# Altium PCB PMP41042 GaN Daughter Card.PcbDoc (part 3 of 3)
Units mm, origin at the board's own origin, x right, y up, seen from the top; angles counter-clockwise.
Board outline 43.43 x 37.33 mm, 6 copper layers (Top Layer, MidLayer1, MidLayer2, MidLayer3, MidLayer4, Bottom Layer), stack 1.844 mm thick; 57 components, 55 nets, 240 pads, 238 vias.
Unrouted connection lines stored in the file: 15.
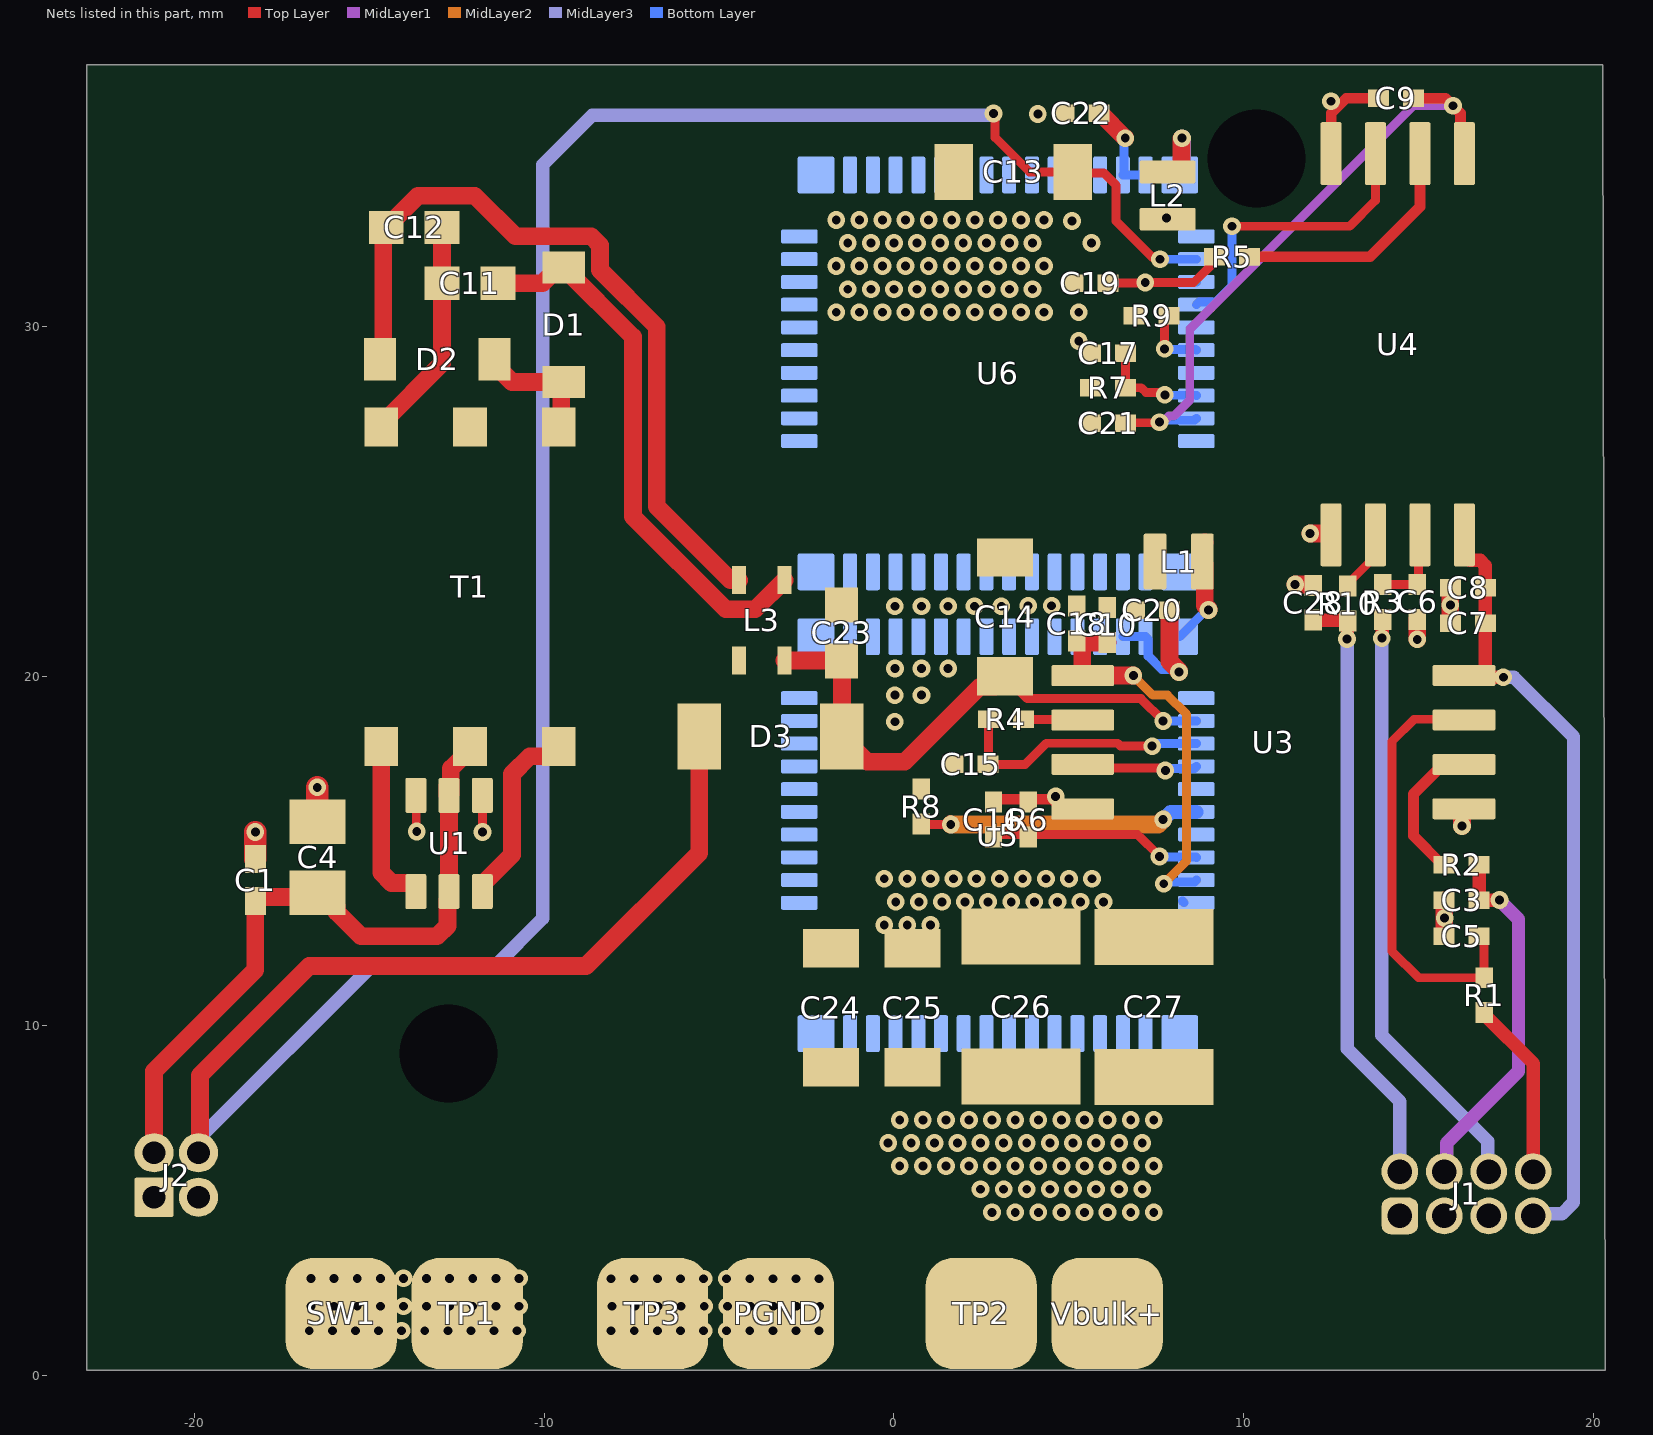
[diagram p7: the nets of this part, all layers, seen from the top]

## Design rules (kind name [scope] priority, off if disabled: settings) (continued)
SilkToSolderMaskClearance SilkToComponentPadClearance [(IsPad or IsFill or IsRegion) and InAnycomponent] p1: minsilkscreentomaskgap=0.025 clearancetoexposedcopper=TRUE
SilkToSolderMaskClearance "Silk to Solder Mask Opening" [All] p2: minsilkscreentomaskgap=0.025 clearancetoexposedcopper=FALSE
SolderMaskExpansion [All] p1: expansion=0.05 istentingtop=FALSE
Width [All] p1: maxlimit=2.54 minlimit=0.152 preferedwidth=0.254 substack1={A02F224D-4808-492E-A71F-5F5656FBF0D4} substack2={B838D286-A00B-4EE2-88E1-F79279CC64B4} substack3={0D253197-D122-4D2B-9584-B8C12AA3806F} substack4={88BCB183-C685-456E-B90A-365A53404C2C} substack5={4C8C2325-90D5-40B8-8B6B-4F66D44EFE25} substack6={553D66F5-99EF-40B1-BA7C-73E3B04B176F} substack7={FF0C9878-5A48-402E-B013-8E2EEFCEDCCB} substack8={5BB5B65B-6C7F-4868-A6AE-66DD57ADDCBD} substack9={65866CD6-1929-42AF-BAA8-019D5E6BA212} substack10={590F0BEA-1E04-4904-B9C9-D9D160075BC2} substack11={B2AC4F48-1A5F-44D7-A91B-3BAADFDAAED0} substack12={DD3D4156-A54D-4E1F-B7FF-E5EF72C45496} substack13={7CC4AE65-1EB7-43C1-8FCA-3677EE54F737} substack14={E8C37195-128A-4AA0-B681-9B6788FCEC2F} substack15={92E0C252-34CC-4501-B85F-B111C59C3287} substack16={732F7058-E977-446F-8A06-ECA871B5D75E} substack17={990DA1BC-A1DE-47D8-A675-B5A4E74B5332} checkconnectedcopper=TRUE
14 further rules are at their usual default settings.

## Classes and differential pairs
component class Header: J1
net class INGND: 5Vp 5Vs 12V AGND Bot_FET_FAULT1 LEG1_HS LEG1_LS NetC5_1 NetC6_1 NetR2_2 NetR10_2 NetU2_12 NetU3_12 PGND Top_FET_FAULT1
net class PGND: 5V_L1 5Vp 12V FAULT_LS NetC17_2 NetC19_2 NetC22_1 NetL2_2 NetR5_1 NetR9_2 NetT1_4 NetT1_6 NetU2_5 NetU6_43 NetU6_47 NetU6_48 NetU6_52 PGND PGND_NC1 PGND_NC2 PGND_NC3 PGND_NC4 PGND_NC5 TEMP_LS
net class VHV: Vbulk+ VHV_NC1 VHV_NC2
net class VSW1NET: 5V_H1 12V ISO_12V_H1 NCT1 NetC11_1 NetC11_2 NetC12_2 NetC15_2 NetC16_2 NetC20_1 NetD1_2 NetL1_2 NetR4_2 NetR8_2 NetT1_5 NetU3_3 NetU3_5 NetU5_43 NetU5_47 NetU5_48 NetU5_52 SW1 SW1_NC1 SW1_NC2 SW1_NC3 SW1_NC4 SW1_NC5 SW1_NC6 SW1_NC7 TEMP_HS_NC1
component class LMG352X: U5 U6

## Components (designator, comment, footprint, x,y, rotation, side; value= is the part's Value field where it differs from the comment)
C1 "C1005X7R1H104K050BB" 0402 -18.258,14.169 r90 top value=0.1uF
C3 "C1005C0G1H680J050BA" 0402L 16.235,13.591 r180 top value=68pF
C4 "GCM21BR71C475KA73L" 0805_HV -16.48,14.819 r90 top value=4.7uF
C5 "04025A101FAT2A" 0402L 16.233,12.56 r180 top value=100pF
C6 "04025A101FAT2A" 0402L 14.965,22.123 r270 top value=100pF
C7 "C1005X7R1H104K050BB" 0402L 16.413,21.514 r180 top value=0.1uF
C8 "C1005X7R1H104K050BB" 0402L 16.413,22.53 r0 top value=0.1uF
C9 "C1005X7R1H104K050BB" 0402L 14.355,36.525 r0 top value=0.1uF
C10 "C1005X7R1H104K050BB" 0402L 6.096,21.463 r90 top value=0.1uF
C11 "C1608X5R1V475K080AC" 0603 -12.121,31.233 r180 top value=4.7uF
C12 "C1608X5R1V475K080AC" 0603 -13.715,32.829 r180 top value=4.7uF
C13 "C3216X7R1E106M160AE" 1206_190 3.417,34.416 r180 top value=10uF
C14 "C3216X7R1E106M160AE" 1206_190 3.179,21.692 r90 top value=10uF
C15 "04025A101FAT2A" 0402L 2.195,17.475 r0 top value=100pF
C16 "04025A101FAT2A" 0402L 2.848,15.9 r270 top value=100pF
C17 "04025A101FAT2A" 0402L 6.126,29.235 r0 top value=100pF
C18 "CL05B224KO5NNNC" 0402L 5.228,21.504 r270 top value=0.22uF
C19 "04025A101FAT2A" 0402L 5.616,31.233 r0 top value=100pF
C20 "GRT155R61E225KE13D" 0402L 7.383,21.89 r180 top value=2.2uF
C21 "CL05B224KO5NNNC" 0402L 6.126,27.229 r0 top value=0.22uF
C22 "GRT155R61E225KE13D" 0402L 5.364,36.093 r180 top value=2.2uF
C23 "C1608X5R1V475K080AC" 0603 -1.494,21.234 r90 top value=4.7uF
C24 "C1206C223KDRACTU" 1206_190 -1.799,10.516 r90 top value=0.022uF
C25 "C1206C223KDRACTU" 1206_190 0.538,10.516 r90 top value=0.022uF
C26 "C1812W104KDRACTU" 1812_254 3.637,10.553 r90 top value=0.1uF
C27 "C1812W104KDRACTU" 1812_254 7.433,10.541 r90 top value=0.1uF
C28 "C1005C0G1H680J050BA" 0402L 11.993,22.098 r90 top value=68pF
D1 "MBR0520LT1G" SOD-123 -9.444,30.048 r270 top value=20V
D2 "MBR0520LT1G" SOD-123 -13.051,29.058 r180 top value=20V
D3 "ES1JAF" SMAF -3.526,18.279 r180 top value=600V
J1 "GRPB042MWCN-RC" Sullins_GRPB042MWCN 16.373,5.2 r90 top
J2 "M50-3900242" FP-M50-3900242_HDR4-MFG -20.519,2.1 r180 top
L1 "SDEM20161T-4R7MS" FP-SDEM20161T-4R7MS_SMD2-MFG 8.144,23.277 r0 top
L2 "SDEM20161T-4R7MS" FP-SDEM20161T-4R7MS_SMD2-MFG 7.829,33.741 r90 top
L3 "ACM2520-601-2P-T002" TDK_ACM2520-2P -3.78,21.593 r270 top
PGND "3621-0-32-15-00-00-08-0" Mill-Max_3621-0-32-xx-00-00-08-0 -3.302,-0.61 r0 top
R1 "RC0402FR-0749R9L" 0402L 16.878,10.876 r90 top value=49.9
R2 "CRCW0402300RJNED" 0402L 16.233,14.605 r180 top value=300
R3 "RC0402FR-0749R9L" 0402L 13.974,22.123 r90 top value=49.9
R4 "RC0402FR-0749R9L" 0402L 3.205,18.771 r0 top value=49.9
R5 "RC0402FR-0749R9L" 0402L 9.669,31.988 r180 top value=49.9
R6 "ERJ-2RKF2003X" 0402L 3.84,15.9 r270 top value=200k
R7 "ERJ-2RKF2003X" 0402L 6.128,28.247 r0 top value=200k
R8 "ERJ-2GE0R00X" 0402L 0.781,16.267 r270 top value=0
R9 "ERJ-2GE0R00X" 0402L 7.37,30.302 r0 top value=0
R10 "CRCW0402300RJNED" 0402L 12.984,22.071 r90 top value=300
SW1 "3621-0-32-15-00-00-08-0" Mill-Max_3621-0-32-xx-00-00-08-0 -15.8,-0.61 r0 top
T1 "760390014" Wurth_760390013 -12.121,22.555 r270 top value=475uH
TP1 "3621-0-32-15-00-00-08-0" Mill-Max_3621-0-32-xx-00-00-08-0 -12.2,-0.61 r0 top
TP2 "3621-0-32-15-00-00-08-0" Mill-Max_3621-0-32-xx-00-00-08-0 2.498,-0.61 r0 top
TP3 "3621-0-32-15-00-00-08-0" Mill-Max_3621-0-32-xx-00-00-08-0 -6.902,-0.61 r0 top
U1 "SN6505BDBVR" DBV0006A_N -12.719,15.215 r90 top
U3 "ISO7721FDWV" DWV0008A#1 10.85,18.11 r0 top
U4 "ISO7721FDWV" DWV0008A#2 14.406,29.489 r270 top
U5 "XMG3522R030QRQSTQ1" RQS0052A-MFG 2.972,15.454 r90 bottom
U6 "XMG3522R030QRQSTQ1" RQS0052A-MFG 2.972,28.655 r90 bottom
Vbulk+ "3621-0-32-15-00-00-08-0" Mill-Max_3621-0-32-xx-00-00-08-0 6.098,-0.61 r0 top

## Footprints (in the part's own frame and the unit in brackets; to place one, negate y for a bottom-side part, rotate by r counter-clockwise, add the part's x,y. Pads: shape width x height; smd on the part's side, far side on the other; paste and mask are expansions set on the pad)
0402 [mm] "0402 from SM-752 data"
  rect 0.8x0.6 smd: 1(-0.6,0) 2(0.6,0)
  silkscreen extent -1.22,-0.52 1.22,0.52, body extent -0.55,-0.3 0.55,0.3, height 0.6
0402L [mm] "0402 from SM-752 data"
  rect 0.6x0.5 smd: 1(-0.5,0) 2(0.5,0)
  body extent -0.55,-0.3 0.55,0.3, height 0.6
0603 [mm] "0603 from SM-752 data"
  rect 1x0.95 smd: 1(-0.8,0) 2(0.8,0)
  silkscreen extent -1.52,-0.69 1.52,0.69, body extent -0.87,-0.47 0.87,0.47, height 1
0805_HV [mil] "0805 with 30mil clearance between pads"
  rect 50x63 smd: 1(-40,0) 2(40,0)
  silkscreen extent -74,-40 74,40, body extent -43,-29 43,29, height 57
1206_190 [mm] "1206_190"
  rect 1.1x1.6 smd: 1(-1.7,0) 2(1.7,0)
  silkscreen extent -0.9,-1 0.9,1, body extent -1.75,-0.95 1.75,0.95, height 1.9
1812_254 [mm] "SMD, 2-Leads, Body 4.8x3.4mm"
  rect 1.6x3.4 smd: 1(-2,0) 2(2,0)
  silkscreen extent -0.8,-1.7 0.8,1.7, body extent -2.4,-1.7 2.4,1.7, height 2.54
DBV0006A_N [mm] "SOT23, 6-Leads, Body 2.9x1.6mm, Pitch 0.95mm, Lead Span 2.8mm, IPC Medium Density"
  rrect17% 1x0.6 smd: 1(-1.375,0.95) 2(-1.375,0) 3(-1.375,-0.95) 4(1.375,-0.95) 5(1.375,0) 6(1.375,0.95)
  silkscreen extent -1.68,-1.55 0.5,1.55, body extent -1.42,-1.46 1.42,1.46, height 1.12
DWV0008A#1 [mm] "SOIC, 8-Leads, Body 5.95x7.6mm (max), Pitch 1.27mm"
  rrect17% 1.8x0.6 smd: 1(-5.45,1.905) 2(-5.45,0.635) 3(-5.45,-0.635) 4(-5.45,-1.905) 5(5.45,-1.905) 6(5.45,-0.635) 7(5.45,0.635) 8(5.45,1.905)
  silkscreen extent -6.25,-2.95 2.98,2.95, body extent -5.77,-2.92 5.77,2.93, height 2.67
DWV0008A#2 [mm] "SOIC, 8-Leads, Body 5.95x7.6mm (max), Pitch 1.27mm"
  rrect17% 1.8x0.6 smd: 1(-5.45,1.905) 2(-5.45,0.635) 3(-5.45,-0.635) 4(-5.45,-1.905) 5(5.45,-1.905) 6(5.45,-0.635) 7(5.45,0.635) 8(5.45,1.905)
  silkscreen extent -6.25,-2.95 2.98,2.95, body extent -5.77,-2.92 5.77,2.93, height 2.67
FP-M50-3900242_HDR4-MFG [mm]
  rrect9% 1.12x1.12 hole 0.65 paste-1000 mask+0: 1(0.635,-3)
  round 1.12 hole 0.65 paste-1000 mask+0: 2(0.635,-4.27) 3(-0.635,-3) 4(-0.635,-4.27)
  silkscreen extent -1.47,-3.12 1.87,0.58, body extent -1.57,-4.93 1.57,4.72, height 0.25
FP-SDEM20161T-4R7MS_SMD2-MFG [mm]
  rrect15% 0.65x1.6 smd paste+0 mask+0: 1(-0.675,0) 2(0.675,0)
  silkscreen extent -1.05,-1.22 1.05,1.2, body extent -1.15,-0.95 1.15,0.95, height 0.25
Mill-Max_3621-0-32-xx-00-00-08-0 [mm] "PCB Pin, 0.04\" DIA, R/A, Edge-Mount"
  rrect50% 3.18x3.18 smd: 1(0,2.388)
  body extent -1.59,-5.06 1.59,3.98, height 1.57
RQS0052A-MFG [mm]
  rrect10% 1.05x1.05 smd paste+0 mask+0: 1(-5.675,5.2) 16(-5.675,-5.2) 27(5.675,-5.2) 42(5.675,5.2)
  rrect25% 1.05x0.4 smd paste+0 mask+0: 2(-5.675,4.225) 3(-5.675,3.575) 4(-5.675,2.925) 5(-5.675,2.275) 6(-5.675,1.625) 7(-5.675,0.975) 8(-5.675,0.325) 9(-5.675,-0.325) 10(-5.675,-0.975) 11(-5.675,-1.625) 12(-5.675,-2.275) 13(-5.675,-2.925) 14(-5.675,-3.575) 15(-5.675,-4.225) 28(5.675,-4.225) 29(5.675,-3.575) 30(5.675,-2.925) 31(5.675,-2.275) 32(5.675,-1.625) 33(5.675,-0.975) 34(5.675,-0.325) 35(5.675,0.325) 36(5.675,0.975) 37(5.675,1.625) 38(5.675,2.275) 39(5.675,2.925) 40(5.675,3.575) 41(5.675,4.225)
  rrect25% 0.4x1.05 smd paste+0 mask+0: 17(-1.935,-5.675) 18(-1.285,-5.675) 19(-0.635,-5.675) 20(0.015,-5.675) 21(0.665,-5.675) 22(1.315,-5.675) 23(1.965,-5.675) 24(2.615,-5.675) 25(3.265,-5.675) 26(3.915,-5.675) 43(3.915,5.675) 44(3.265,5.675) 45(2.615,5.675) 46(1.965,5.675) 47(1.315,5.675) 48(0.665,5.675) 49(0.015,5.675) 50(-0.635,5.675) 51(-1.285,5.675) 52(-1.935,5.675)
  silkscreen extent -6.9,-6.05 4.77,6.05, body extent -6,-6 6,6, height 1
SMAF [mm] "SMD, 2-Leads, Body 3.8x2.5mm"
  rect 1.24x1.89 smd: 1(-2.04,0) 2(2.04,0)
  silkscreen extent -3.4,-1.3 2.8,1.3, body extent -2.35,-1.25 2.35,1.25, height 1
SOD-123 [mm] "On Semi recommended land pattern"
  rect 0.915x1.22 smd: 1(-1.637,0) 2(1.637,0)
  silkscreen extent -2.74,-1.17 2.03,1.17, body extent -1.93,-0.9 1.93,0.9, height 1.35
Sullins_GRPB042MWCN [mm] "Header, 1.27mm, 4x2, R/A, TH"
  rrect50% 1.05x1.05 hole 0.7: 1(-0.635,1.905)
  round 1.05 hole 0.7: 2(0.635,1.905) 3(-0.635,0.635) 4(0.635,0.635) 5(-0.635,-0.635) 6(0.635,-0.635) 7(-0.635,-1.905) 8(0.635,-1.905)
  body extent -5.28,-2.54 0.84,2.54, height 3.4
TDK_ACM2520-2P [mm] "SMD, 4-Leads, Body 2.5x2mm"
  rect 0.8x0.4 smd: 1(-1.15,0.65) 2(-1.15,-0.65) 3(1.15,-0.65) 4(1.15,0.65)
  silkscreen extent -1.45,-1.2 1.45,1.4, body extent -1.35,-1.1 1.35,1.1, height 1.3
Wurth_760390013 [mil] "Wurth"
  rect 44x38 smd: 1(-180,100) 2(-180,0) 3(-180,-100) 4(180,-100) 5(180,0) 6(180,100)
  silkscreen extent -190,-133 85,145, body extent -198,-135 198,130, height 166

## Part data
C1 C7 C8 C9 C10: library part CMP-0006297-2, "CAP, CERM, 0.1 uF, 50 V, +/- 10%, X7R, 0402", Alternate Manufacturer="Wurth Elektronik", Alternate PartNumber=885012205037, Cap_Case=0402, Manufacturer=TDK, Supplier Part Number 1=445-5932-1-ND, TempCo=X7R, Tolerance_%=10%, Value1="0.039064 ohm", Value2=50V, ValueDisplayed=0.1uF
C3 C28: library part CMP-0006251-2, "CAP, CERM, 68 pF, 50 V, +/- 5%, C0G/NP0, 0402", Alternate Manufacturer=Murata, Alternate PartNumber=GRM1555C1H680JA01D, Cap_Case=0402, Manufacturer=TDK, Supplier Part Number 1=445-1245-1-ND, TempCo=C0G/NP0, Tolerance_%=5%, Value1=Unknown, Value2=50V, ValueDisplayed=68pF
C4: library part CMP-0008020-2, "CAP, CERM, 4.7 uF, 16 V, +/- 10%, X7R, AEC-Q200 Grade 1, 0805", Cap_Case=0805, Manufacturer=MuRata, Supplier Part Number 1=490-5332-1-ND, TempCo=X7R, Tolerance_%=10%, Value1=Unknown, Value2=16V, ValueDisplayed=4.7uF
C5 C6 C15 C16 C17 C19: library part CMP-0006196-2, "CAP, CERM, 100 pF, 50 V, +/- 1%, C0G/NP0, 0402", Cap_Case=0402, Manufacturer=AVX, Supplier Part Number 1=478-3658-1-ND, TempCo=C0G/NP0, Tolerance_%=1%, Value1=Unknown, Value2=50V, ValueDisplayed=100pF
C11 C12 C23: library part CMP-0007022-5, "CAP, CERM, 4.7 uF, 35 V, +/- 10%, X5R, 0603", Cap_Case=0603, Manufacturer=TDK, Supplier Part Number 1=445-9064-1-ND, TempCo=X5R, Tolerance_%=10%, Value1="0.003728 ohm", Value2=35V, ValueDisplayed=4.7uF
C13 C14: library part CMP-0008692-2, "CAP, CERM, 10 uF, 25 V, +/- 20%, X7R, 1206_190", Cap_Case=1206, Manufacturer=TDK, Supplier Part Number 1=445-6812-1-ND, TempCo=X7R, Tolerance_%=20%, Value1=Unknown, Value2=25V, ValueDisplayed=10uF
C18 C21: library part CMP-0860563-1, "CAP, CERM, 0.22 µF, 16 V,+/- 10%, X7R, 0402", Cap_Case=0402, Manufacturer="Samsung Electro-Mechanics", TempCo=X7R, Tolerance_%=10%, Value2=16V, ValueDisplayed=0.22µF
C20 C22: library part CMP-0006716-2, "CAP, CERM, 2.2 uF, 25 V, +/- 10%, X5R, AEC-Q200 Grade 3, 0402", Cap_Case=0402, Manufacturer=MuRata, Supplier Part Number 1=490-12267-1-ND, TempCo=X5R, Tolerance_%=10%, Value1=Unknown, Value2=25V, ValueDisplayed=2.2uF
C24 C25: library part CMP-0084048-1, "CAP, CERM, 0.022 µF, 1000 V,+/- 10%, X7R, AEC-Q200 Grade 1, 1206", Cap_Case=1206, Manufacturer=Kemet, TempCo=X7R, Tolerance_%=10%, Value2=1000V, ValueDisplayed=0.022µF
C26 C27: library part CMP-0009326-2, "CAP, CERM, 0.1 uF, 1000 V, +/- 10%, X7R, 1812", Cap_Case=1812, Manufacturer=Kemet, Supplier Part Number 1=399-6523-1-ND, TempCo=X7R, Tolerance_%=10%, Value1=Unknown, Value2=1000V, ValueDisplayed=0.1uF
D1 D2: library part CMP-0028524-2, "Diode, Schottky, 20 V, 0.5 A, SOD-123", Manufacturer="ON Semiconductor", Value1=0.5A, Value2=0.385V
D3: library part CMP-0029162-2, "Diode, Ultrafast, 600 V, 1 A, AEC-Q101, SMAF", Manufacturer="Fairchild Semiconductor", Value1=1A, Value2=1.7V
J1: library part CMP-0086278-1, "Header, 1.27mm, 4x2, Gold, R/A, TH", Current_A=1A, Manufacturer="Sullins Connector Solutions", Voltage_V=500V
J2: library part CMP-0097643-1, Current_A=1A, Digikey Part Number=M50-3900242-ND, Manufacturer=Harwin, Mouser Part Number=855-M50-3900242, Operating Temperature Range="-40°C to +105°C"
L1 L2: library part CMP-0089347-1, "4.7µH Unshielded Inductor 1.1A 426mOhm Max 0806 (2016 Metric)", Digikey Part Number=2037-SDEM20161T-4R7MSCT-ND, Manufacturer=Cyntec, Operating Temperature Range="-55°C to +125°C", Test Frequency=1MHz, Tolerance_%=20%
L3: library part CMP-0013161-2, "Coupled inductor, 0.2 A, 0.45 ohm, SMD", Manufacturer=TDK, Supplier Part Number 1=445-8930-1-ND
PGND SW1 TP1 TP2 TP3 Vbulk+: library part CMP-0082316-1, Manufacturer=Mill-Max, Supplier Part Number 1=575-3621032150000
R1 R3 R4 R5: library part CMP-0026738-1, "RES, 49.9, 1%, 0.063 W, 0402", Manufacturer="Yageo America", Power_W=63mW, Supplier Part Number 1=311-49.9LRCT-ND, TempCo="100 ppm/C", Tolerance_%=1%, Value2=0.063W, Value_Code=49R9, ValueDisplayed=49.9
R2 R10: library part CMP-0026902-3, "RES, 300, 5%, 0.063 W, AEC-Q200 Grade 0, 0402", Manufacturer=Vishay-Dale, Power_W=63mW, Supplier Part Number 1=541-300JCT-ND, TempCo="200 ppm/C", Tolerance_%=5%, Value2=0.063W, Value_Code=300R, ValueDisplayed=300
R6 R7: library part CMP-0026677-1, "RES, 200 k, 1%, 0.1 W, 0402", Manufacturer=Panasonic, Power_W=100mW, Supplier Part Number 1=P200KLCT-ND, TempCo="100 ppm/C", Tolerance_%=1%, Value2=0.1W, Value_Code=200k
R8 R9: library part CMP-0026992-3, "RES, 0, 5%, 0.1 W, AEC-Q200 Grade 0, 0402", Manufacturer=Panasonic, Power_W=100mW, Supplier Part Number 1=P0.0JCT-ND, TempCo="600 ppm/C", Tolerance_%=5%, Value2=0.1W, Value_Code=0000, ValueDisplayed=0
T1: library part CMP-0030718-1, "Transformer, 475uH, SMT", Manufacturer="Wurth Elektronik", Supplier Part Number 1=732-4458-1-ND, ValueDisplayed=475uH
U1: library part CMP-0076095-1, "Low-Noise 1 A, 420 kHz Transformer Driver, DBV0006A (SOT-23-6)", Alternate Manufacturer="Texas Instruments", Alternate PartNumber=SN6505BDBVT
U3 U4: library part CMP-0085676-1, "High Speed, Robust EMC Reinforced Dual-Channel Digital Isolator, DWV0008A (SOIC-8)", Alternate Manufacturer="Texas Instruments", Alternate PartNumber=ISO7721FDWVR, Operating Temperature Range="-55 to 125 C", Rating=Catalog
U5 U6: library part CMP-0092112-1, "650-V 30-mΩ GaN FET with Integrated Driver, Protection, and Temperature Reporting", Manufacturer="Texas Instruments", Max Supply Voltage=18V, Min Supply Voltage=7.5V, Nominal Supply Current=700-16000uA, Operating Temperature Range="-40°C to +125°C", Output Voltage=520V, PartNumber=XMG3522R050QRQSTQ1

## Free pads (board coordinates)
  round 1.524 hole 2.8: 1(-12.734,9.208) 1(10.368,34.804)

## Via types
v1: diameter 0.508, hole 0.254, Top Layer to Bottom Layer, tented both sides, 178 vias
v2: diameter 0.508, hole 0.254, Top Layer to Bottom Layer, tented bottom, 60 vias

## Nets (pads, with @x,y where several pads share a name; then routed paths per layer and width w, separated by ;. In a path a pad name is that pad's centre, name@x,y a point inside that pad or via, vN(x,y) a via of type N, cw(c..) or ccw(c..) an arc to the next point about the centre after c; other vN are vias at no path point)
5V_H1: C10.1 C18.2 U3.1 U5.51 | length 11.2
  Top Layer w0.508: C10.1@6.116,20.963 5.388,20.963 5.388,20.028 U3.1@5.4,20.015 v1(6.846,20.015)
  MidLayer2 w0.254: v1(6.846,20.015) 7.402,19.459 7.822,19.459 8.371,18.91 8.371,14.719 v1(7.717,14.065)
  Bottom Layer w0.254: v1(7.717,14.065) 7.769,14.117 8.595,14.117 U5.51@8.647,14.169
5V_L1: C9.2 C21.2 U4.1 U6.51 | length 18.1
  Top Layer w0.254: C21.2@6.626,27.229 6.642,27.245 7.579,27.245 v1(7.595,27.261)
  Top Layer w0.305: C9.2@14.855,36.525 15.77,36.525 v1(15.986,36.309) 16.202,36.093 16.202,35.049 U4.1@16.311,34.939
  MidLayer1 w0.254: v1(7.595,27.261) 7.691,27.261 7.864,27.434 7.999,27.434 8.459,27.893 8.459,29.921 14.847,36.309 v1(15.986,36.309)
  Bottom Layer w0.254: v1(7.595,27.261) 7.65,27.316 8.593,27.316 U6.51@8.647,27.37
5Vp: C1.1 C4.1 J2.2 T1.5 U1.2 U1.5 | length 20.2
  Top Layer w0.508: J2.2@-21.154,6.37 -21.154,8.701 -18.258,11.597 C1.1@-18.258,13.569 -18.258,13.64 -18.212,13.686 -16.597,13.686 C4.1@-16.48,13.803 -16.315,13.803 -15.934,13.422 -15.934,13.257 -15.236,12.559 -13.062,12.559 -12.765,12.857 -12.765,13.594 U1.2@-12.719,13.64 ; U1.5@-12.762,16.59 U1.5@-12.762,16.851 ; U1.2@-12.719,13.84 U1.5@-12.719,16.59 -12.673,16.636 -12.673,17.355 -12.121,17.907 T1.5@-12.121,17.983
5Vs: C7.1 C8.2 J1.7 U3.8 U4.8 | length 22.8
  Top Layer w0.381: U3.8@16.3,20.015 16.913,20.015 C8.2@16.913,22.53 16.913,23.161 16.764,23.31 16.484,23.31 16.311,23.483 U4.8@16.311,24.039 ; U3.8@16.74,19.969 v1(17.426,19.969) ; J1.7@18.528,4.572 J1.7@18.583,4.627
  MidLayer3 w0.381: v1(17.426,19.969) 17.729,19.969 19.431,18.267 19.431,4.953 19.105,4.627 J1.7@18.583,4.627
12V: C13.1 D3.2 J2.4 U6.44 | length 79
  Top Layer w0.254: v1(2.848,36.088) 2.891,36.046 2.891,35.402 3.877,34.416 C13.1@5.117,34.416 5.143,34.39 5.997,34.39 6.355,34.031 6.355,33.012 7.379,31.988 7.542,31.988 v1(7.61,31.92)
  Top Layer w0.508: J2.4@-19.843,6.223 -19.843,8.583 -16.717,11.709 -8.802,11.709 -5.566,14.946 D3.2@-5.566,18.279
  MidLayer3 w0.381: J2.4@-19.767,6.487 -19.742,6.511 -19.742,6.904 -14.937,11.709 -11.405,11.709 -10.042,13.072 -10.042,34.622 -8.624,36.04 2.799,36.04 v1(2.848,36.088)
  MidLayer3 w0.508: J2.4@-19.884,6.37 J2.4@-19.767,6.487
  Bottom Layer w0.254: v1(7.61,31.92) U6.44@8.647,31.92
AGND: C3.2 C5.2 C6.2 C7.2 C8.1 C28.2 J1.1 J1.3 J1.5 U3.5 U4.5 | length 4.3
  Top Layer w0.508: v1(11.473,22.618) 11.989,22.618 11.993,22.614 C28.2@11.993,22.598 ; v1(11.903,24.078) 12.463,24.078 U4.5@12.501,24.039 ; v1(14.965,21.053) C6.2@14.965,21.623 ; C5.2@15.733,12.56 15.734,12.562 15.734,13.59 C3.2@15.735,13.591 ; C8.1@15.911,22.526 15.911,21.516 C7.2@15.913,21.514 ; v1(16.243,15.717) 16.243,16.159 16.254,16.159 U3.5@16.3,16.205
  other v1: 15.748,13.081 15.911,22.031
Bot_FET_FAULT1: C28.1 J1.2 R10.1 | length 17.3
  Top Layer w0.381: C28.1@11.993,21.598 R10.1@12.984,21.598 ; v1@12.971,21.073 R10.1@12.971,21.585
  MidLayer3 w0.381: v1@12.971,21.073 v1(12.959,21.06) 12.959,9.348 14.468,7.839 J1.2@14.468,5.935
FAULT_LS: U4.3 U6.46 | length 8.7
  Top Layer w0.254: v1(9.669,32.863) 13.03,32.863 13.771,33.604 U4.3@13.771,34.939
  Bottom Layer w0.254: U6.46@8.647,30.62 8.72,30.693 9.197,30.693 9.669,31.165 v1(9.669,32.863)
ISO_12V_H1: C14.1 C23.1 D3.1 L3.4 U5.44 | length 15.8
  Top Layer w0.254: C14.1@3.179,19.992 3.814,19.357 7.062,19.357 v1(7.7,18.719)
  Top Layer w0.508: L3.4@-3.13,20.443 -1.503,20.443 C23.1@-1.494,20.434 -1.486,20.426 D3.1@-1.486,18.279 -0.761,17.554 0.311,17.554 2.453,19.696 2.883,19.696 C14.1@3.179,19.992
  Bottom Layer w0.254: v1(7.7,18.719) U5.44@8.647,18.719
LEG1_HS: J1.8 R1.1 | length 5
  Top Layer w0.381: R1.1@16.861,10.393 R1.1@16.878,10.376 16.878,10.326 18.278,8.926 J1.8@18.278,5.935
LEG1_LS: J1.6 R3.1 | length 17
  Top Layer w0.254: v1(13.951,21.085) v1@13.963,21.097 ; R3.1@13.963,21.612 R3.1@13.974,21.623
  Top Layer w0.381: v1@13.963,21.097 R3.1@13.963,21.612
  MidLayer3 w0.381: v1(13.951,21.085) 13.951,9.732 16.984,6.7 16.984,5.959 J1.6@17.008,5.935
NCT1: T1.2
NetC5_1: C5.1 R1.2 U3.7 | length 12.5
  Top Layer w0.254: U3.7@16.3,18.745 16.28,18.766 14.876,18.766 14.24,18.13 14.24,12.138 15.002,11.376 R1.2@16.878,11.376 16.878,12.437 16.755,12.56 C5.1@16.733,12.56 C5.1@16.738,12.555
NetC6_1: C6.1 R3.2 U4.7 | length 2.5
  Top Layer w0.254: R3.2@13.974,22.623 C6.1@14.965,22.623 15.003,22.661 15.003,24.001 U4.7@15.041,24.039 U4.7@15.003,24.078
NetC11_1: C11.1 D1.1 L3.1 | length 15.8
  Top Layer w0.508: C11.1@-11.321,31.233 -10.05,31.233 -9.597,31.686 D1.1@-9.444,31.686 -7.463,29.704 -7.463,24.566 -4.809,21.911 -3.962,21.911 L3.1@-3.13,22.743
NetC11_2: C11.2 C12.1 T1.3 | length 6.5
  Top Layer w0.508: T1.3@-14.661,27.127 -14.661,27.203 -12.921,28.943 C11.2@-12.921,31.233 -12.918,31.236 -12.918,32.826 C12.1@-12.915,32.829 C12.1@-12.846,32.761
NetC12_2: C12.2 D2.2 L3.2 | length 22.3
  Top Layer w0.508: D2.2@-14.689,29.058 -14.602,29.145 -14.602,32.742 C12.2@-14.515,32.829 -13.608,33.736 -11.983,33.736 -10.822,32.575 -8.655,32.575 -8.403,32.322 -8.403,31.614 -6.777,29.989 -6.777,24.85 -4.671,22.743 L3.2@-4.43,22.743
NetC15_2: C15.2 R4.1 U5.45 | length 7.6
  Top Layer w0.254: R4.1@2.554,18.821 R4.1@2.605,18.771 ; R4.1@2.705,18.771 2.7,18.766 2.7,17.48 C15.2@2.695,17.475 3.75,17.475 4.355,18.08 6.397,18.08 6.48,17.997 v1(7.385,17.997)
  Bottom Layer w0.254: v1(7.385,17.997) 7.482,17.997 7.553,18.069 U5.45@8.647,18.069
NetC16_2: C16.2 R6.2 U5.50 | length 6.1
  Top Layer w0.254: C16.2@2.848,15.3 C16.2@2.899,15.25 ; C16.2@2.848,15.477 3.84,15.477 6.964,15.477 v1(7.598,14.843)
  Bottom Layer w0.254: v1(7.598,14.843) 7.61,14.831 8.635,14.831 U5.50@8.647,14.819
NetC17_2: C17.2 R7.2 U6.50 | length 3.1
  Top Layer w0.254: R7.2@6.626,28.245 C17.2@6.626,29.235 ; R7.2@6.673,28.247 7.073,28.247 7.208,28.112 7.679,28.112 v1(7.747,28.044)
  Bottom Layer w0.254: v1@7.7,28.042 7.71,28.031 8.637,28.031 U6.50@8.647,28.02
NetC19_2: C19.2 R5.2 U6.45 | length 4.8
  Top Layer w0.254: C19.2@6.127,31.222 C19.2@6.116,31.233 6.128,31.244 7.176,31.244 v1(7.188,31.256) 8.572,31.256 R5.2@9.169,31.852 ; R5.2@9.169,31.988 R5.2@9.179,31.978
  Bottom Layer w0.254: v1(7.188,31.256) 7.195,31.263 8.64,31.263 U6.45@8.647,31.27
NetC20_1: C20.1 U5.40 U5.41 | length 4.2
  Top Layer w0.508: C20.1@7.883,21.89 7.883,20.417 8.151,20.149 v1(8.151,20.121)
  Bottom Layer w0.254: U5.40@6.547,21.129 U5.41@7.197,21.129 7.27,21.056 7.27,20.581 7.662,20.189 8.083,20.189 v1(8.151,20.121)
NetC22_1: C22.1 U6.40 U6.41 | length 2.8
  Top Layer w0.508: C22.1@5.864,36.093 5.906,36.093 v1@6.616,35.383
  Bottom Layer w0.254: v1(6.616,35.382) 6.582,35.348 6.582,34.365 U6.40@6.547,34.33 U6.41@7.197,34.33
NetD1_2: D1.2 D2.1 T1.1 | length 3.7
  Top Layer w0.508: D2.1@-11.414,29.058 -11.414,28.905 -10.919,28.411 D1.2@-9.444,28.411 -9.513,28.342 -9.513,27.195 T1.1@-9.581,27.127
NetL1_2: L1.2 U5.42 | length 3.2
  Top Layer w0.508: L1.2@8.89,23.823 8.819,23.752 L1.2@8.819,23.277 8.89,23.206 8.89,22.02 8.992,21.918 v1(8.992,21.89) v1@8.973,21.91
  Bottom Layer w0.254: U5.42@8.172,21.129 8.934,21.89 v1(8.992,21.89)
NetL2_2: L2.2 U6.42 | length 2.4
  Top Layer w0.508: L2.2@7.829,34.416 8.151,34.416 8.222,34.487 8.222,35.363 v1(8.241,35.382)
  Bottom Layer w0.254: U6.42@8.172,34.33 U6.42@8.241,34.399
  Bottom Layer w0.508: U6.42@8.241,34.399 v1(8.241,35.382)
NetR2_2: R2.2 U3.6 | length 4.2
  Top Layer w0.305: R2.2@15.733,14.605 15.683,14.605 14.855,15.432 14.855,16.63 15.7,17.475 U3.6@16.3,17.475
NetR4_2: R4.2 U3.2 | length 1.7
  Top Layer w0.254: R4.2@3.705,18.771 3.718,18.758 5.388,18.758 U3.2@5.4,18.745
NetR5_1: R5.1 U4.2 | length 7.1
  Top Layer w0.305: R5.1@10.014,31.988 13.613,31.988 15.041,33.416 U4.2@15.041,34.939
NetR8_2: R8.2 U5.48 | length 8.1
  Top Layer w0.254: R8.2@0.776,15.772 R8.2@0.781,15.767 0.785,15.763 1.623,15.763 v1(1.627,15.759) v1@1.632,15.764
  MidLayer2 w0.254: v1@1.605,15.9 v1@1.627,15.9
  MidLayer2 w0.508: v1(1.627,15.759) 7.558,15.759 v1(7.7,15.9)
  Bottom Layer w0.254: U5.48@8.604,16.162 U5.48@8.647,16.119
  Bottom Layer w0.406: v1(7.7,15.9) 7.918,16.119 U5.48@8.647,16.119
NetR9_2: R9.2 U6.48 | length 1.9
  Top Layer w0.254: v1(7.743,29.358) 7.743,30.179 7.866,30.302 R9.2@7.87,30.302
  Bottom Layer w0.254: v1(7.743,29.358) 7.762,29.339 8.628,29.339 U6.48@8.647,29.32
NetR10_2: R10.2 U4.6 | length 1.8
  Top Layer w0.254: R10.2@12.984,22.598 12.984,22.648 13.598,23.262 13.598,23.866 U4.6@13.771,24.039
NetT1_4: T1.4 U1.1 | length 4.9
  Top Layer w0.508: T1.4@-14.661,17.983 -14.661,14.383 -14.363,14.086 -13.715,14.086 -13.669,14.04 U1.1@-13.669,13.84
NetT1_6: T1.6 U1.3 | length 5.4
  Top Layer w0.508: U1.3@-11.769,13.84 -11.769,14.04 -10.919,14.89 -10.919,17.2 -10.41,17.709 -9.81,17.709 -9.581,17.937 T1.6@-9.581,17.983
NetU3_3: U3.3 U5.46 | length 3.4
  Top Layer w0.254: U3.3@5.4,17.475 5.502,17.373 7.694,17.373 v1(7.762,17.305)
  Bottom Layer w0.254: v1(7.762,17.305) 7.818,17.362 8.591,17.362 U5.46@8.647,17.419
PGND: C1.2 C4.2 C9.1 C13.2 C17.1 C19.1 C21.1 C22.2 C24.2 C25.2 C26.2 C27.2 J2.1 J2.3 L2.1 PGND.1 R7.1 R9.1 TP3.1 U1.4 U1.6 U4.4 U6.18 U6.19 U6.20 U6.21 U6.22 U6.23 U6.24 U6.25 U6.26 U6.28 U6.29 U6.30 U6.31 U6.32 U6.33 U6.34 U6.35 U6.36 U6.37 U6.38 U6.39 | length 6.6
  Top Layer w0.254: U1.6@-13.669,16.59 -13.656,16.577 -13.656,15.57 v1(-13.643,15.557) ; U1.4@-11.769,16.59 -11.766,16.587 -11.766,15.549 v1(-11.763,15.547)
  Top Layer w0.305: U4.4@12.501,34.939 12.501,36.093 12.933,36.525 C9.1@13.855,36.525
  Top Layer w0.508: v1(7.797,33.098) L2.1@7.829,33.066
  Top Layer w0.635: C1.2@-18.258,14.769 v1(-18.258,15.541) ; v1(-16.486,16.82) -16.486,15.841 C4.2@-16.48,15.835
  other v1: -0.277,12.886 0.383,12.886 1.044,12.886 0.053,13.546 0.713,13.546 1.374,13.546 2.034,13.546 2.695,13.546 3.355,13.546 4.015,13.546 4.676,13.546 5.336,13.546 5.997,13.546 -0.277,14.206 0.383,14.206 1.044,14.206 1.704,14.206 2.364,14.206 3.025,14.206 3.685,14.206 4.346,14.206 5.006,14.206 5.666,14.206 5.286,29.585 -1.648,30.403 -0.988,30.403 -0.327,30.403 0.333,30.403 0.994,30.403 1.654,30.403 2.314,30.403 2.975,30.403 3.635,30.403 4.296,30.403 5.286,30.403 -1.318,31.063 -0.657,31.063 0.003,31.063 0.663,31.063 1.324,31.063 1.984,31.063 2.645,31.063 3.305,31.063 3.965,31.063 -1.648,31.724 -0.988,31.724 -0.327,31.724 0.333,31.724 0.994,31.724 1.654,31.724 2.314,31.724 2.975,31.724 3.635,31.724 4.296,31.724 -1.318,32.384 -0.657,32.384 0.003,32.384 0.663,32.384 1.324,32.384 1.984,32.384 2.645,32.384 3.305,32.384 3.965,32.384 5.651,32.384 5.096,33.012 -1.648,33.045 -0.988,33.045 -0.327,33.045 0.333,33.045 0.994,33.045 1.654,33.045 2.314,33.045 2.975,33.045 3.635,33.045 4.296,33.045 4.116,36.076 12.501,36.437
  other v2: -8.084,1.283 -7.424,1.283 -6.763,1.283 -6.103,1.283 -5.443,1.283 -4.782,1.283 -4.122,1.283 -3.461,1.283 -2.801,1.283 -2.141,1.283 -8.064,1.984 -7.403,1.984 -6.743,1.984 -6.083,1.984 -5.422,1.984 -4.762,1.984 -4.101,1.984 -3.441,1.984 -2.781,1.984 -2.12,1.984 -8.084,2.769 -7.424,2.769 -6.763,2.769 -6.103,2.769 -5.443,2.769 -4.782,2.769 -4.122,2.769 -3.461,2.769 -2.801,2.769 -2.141,2.769
PGND_NC1: U6.17
PGND_NC2: U6.27
PGND_NC3: U6.43
PGND_NC4: U6.47
PGND_NC5: U6.52
SW1: C10.2 C14.2 C15.1 C16.1 C18.1 C20.2 C23.2 L1.1 L3.3 R6.1 R8.1 SW1.1 TP1.1 U3.4 U5.18 U5.19 U5.20 U5.21 U5.22 U5.23 U5.24 U5.25 U5.26 U5.28 U5.29 U5.30 U5.31 U5.32 U5.33 U5.34 U5.35 U5.36 U5.37 U5.38 U5.39 U6.2 U6.3 U6.4 U6.5 U6.6 U6.7 U6.8 U6.9 U6.10 U6.11 U6.12 U6.13 U6.14 U6.15 | length 2.7
  Top Layer w0.305: C16.1@2.848,16.477 3.84,16.477 4.025,16.477 4.529,16.477 4.8,16.205 U3.4@5.4,16.205 ; C20.2@6.729,21.89 C20.2@6.783,21.89
  other v1: 4.626,16.561 0.027,18.694 0.027,19.455 0.792,19.455 0.03,20.218 0.792,20.218 1.551,20.218 0.027,21.996 0.788,21.996 1.551,21.996 2.304,21.996 3.073,21.996 3.84,22.013 4.511,22.013
  other v2: -16.717,1.283 -16.057,1.283 -15.396,1.283 -14.736,1.283 -14.076,1.283 -13.415,1.283 -12.755,1.283 -12.094,1.283 -11.434,1.283 -10.774,1.283 -16.664,1.984 -16.004,1.984 -15.344,1.984 -14.683,1.984 -14.023,1.984 -13.362,1.984 -12.702,1.984 -12.042,1.984 -11.381,1.984 -10.721,1.984 -16.664,2.781 -16.004,2.781 -15.344,2.781 -14.683,2.781 -14.023,2.781 -13.362,2.781 -12.702,2.781 -12.042,2.781 -11.381,2.781 -10.721,2.781
SW1_NC1: U5.17
SW1_NC2: U5.27
SW1_NC3: U5.43
SW1_NC4: U5.47
SW1_NC5: U5.52 | length 0.1
  Bottom Layer w0.254: U5.52@8.249,13.566 U5.52@8.296,13.519
SW1_NC6: U6.1
SW1_NC7: U6.16
TEMP_HS_NC1: U5.49
TEMP_LS: U6.49
Top_FET_FAULT1: C3.1 J1.4 R2.1 | length 10.6
  Top Layer w0.381: J1.4@15.738,5.935 J1.4@15.89,6.087 ; R2.1@16.733,14.605 16.734,14.604 16.734,13.593 C3.1@16.735,13.591 16.739,13.595 17.309,13.595 v1(17.313,13.6)
  MidLayer1 w0.381: J1.4@15.738,5.935 15.811,6.008 15.811,6.65 17.859,8.699 17.859,13.053 v1(17.313,13.6)
Vbulk+: C24.1 C25.1 C26.1 C27.1 TP2.1 U5.2 U5.3 U5.4 U5.5 U5.6 U5.7 U5.8 U5.9 U5.10 U5.11 U5.12 U5.13 U5.14 U5.15 Vbulk+.1
  other v1: 2.809,4.669 3.469,4.669 4.13,4.669 4.79,4.669 5.45,4.669 6.111,4.669 6.771,4.669 7.432,4.669 2.479,5.329 3.139,5.329 3.799,5.329 4.46,5.329 5.12,5.329 5.781,5.329 6.441,5.329 7.101,5.329 0.167,5.99 0.828,5.99 1.488,5.99 2.148,5.99 2.809,5.99 3.469,5.99 4.13,5.99 4.79,5.99 5.45,5.99 6.111,5.99 6.771,5.99 7.432,5.99 -0.163,6.65 0.497,6.65 1.158,6.65 1.818,6.65 2.479,6.65 3.139,6.65 3.799,6.65 4.46,6.65 5.12,6.65 5.781,6.65 6.441,6.65 7.101,6.65 0.167,7.311 0.828,7.311 1.488,7.311 2.148,7.311 2.809,7.311 3.469,7.311 4.13,7.311 4.79,7.311 5.45,7.311 6.111,7.311 6.771,7.311 7.432,7.311
VHV_NC1: U5.1
VHV_NC2: U5.16

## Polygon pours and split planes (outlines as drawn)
SW1 on Bottom Layer "NONET_L-01_P-001" (solid, pour order 124): -10.216,7.515 -17.496,3.458 -17.496,0.152 -10.41,0.152 -10.41,3.235 -9.961,3.683 -10.187,3.458 -6.511,6.169 -6.511,8.145 -10.127,8.145 -10.216,8.056
PGND on Bottom Layer "PGND_L06_P098" (solid, remove dead copper, pour order 98): 12.959,32.385 9.988,32.385 7.18,29.515 5.651,29.515 5.651,37.359 13.951,37.359 13.951,33.377
Vbulk+ on Bottom Layer "VBULK+_L06_P077" (solid, remove dead copper, pour order 77): -1.947,10.493 -2.782,9.657 -2.782,7.514 -0.657,5.39 -0.637,5.41 0.83,5.41 0.83,0.152 7.818,0.152 7.818,5.385 9.41,5.385 9.41,9.645 8.563,10.493
AGND on Bottom Layer "AGND_L06_P061" (solid, remove dead copper, pour order 61): 10.646,23.765 11.849,24.968 17.958,24.968 19.812,23.114 19.812,0.153 10.646,0.153
SW1 on Bottom Layer "SW1_L06_P036" (solid, remove dead copper, pour order 36): -1.684,14.874 -3.681,12.877 -3.681,23.102 -2.836,23.947 7.276,23.947 7.504,23.718 7.502,21.67 6.069,20.229 3.671,20.229
PGND on Bottom Layer "PGND_L06_P037" (solid, remove dead copper, pour order 37): 6.354,29.515 5.821,28.981 5.135,28.981 4.78,29.337 4.78,33.401 4.597,33.401 4.597,26.687 3.513,25.603 -2.987,25.603 -3.013,25.578 -3.704,26.269 -3.704,34.932 -3.53,34.932 -1.491,36.971 6.354,36.971
SW1 on Bottom Layer "SW1_L06_P122" (solid, pour order 122): -10.216,16.596 -3.418,23.393 -3.145,23.393 -3.145,22.826 -1.636,21.316 -1.636,14.997 -6.511,10.121 -6.511,6.169 -10.216,6.169
SW1 on MidLayer2 "SW1_L03_P040" (solid, pour order 40): -6.614,10.019 -1.636,14.997 -1.636,16.596 -10.216,16.596 -10.216,6.093 -6.614,6.093
SW1 on MidLayer2 "NONET_L-01_P-001" (solid, pour order 123): -10.172,8.101 -17.496,3.458 -17.496,0.152 -10.41,0.152 -10.41,3.293 -6.511,6.169
Vbulk+ on MidLayer2 "VBULK+_L03_P074" (solid, remove dead copper, pour order 74): -0.988,7.924 -0.988,5.72 -0.657,5.39 0.83,5.39 0.83,0.153 7.818,0.153 7.818,5.385 9.41,5.385 9.41,7.924
PGND on MidLayer2 "PGND_L03_P094" (solid, remove dead copper, pour order 94): 3.513,37.359 3.513,34.649 4.933,33.229 5.461,33.757 5.461,37.359
PGND on MidLayer2 "PGND_L03_P069" (solid, remove dead copper, pour order 69): 11.891,37.359 11.891,33.956 5.461,33.956 4.83,33.325 4.83,27.026 8.741,27.026 8.765,27.049 8.765,29.588 11.558,32.381 17.631,32.381 17.631,37.335 17.607,37.359
SW1 on MidLayer2 "SW1_L03_P039" (solid, pour order 39): -10.187,14.89 -10.187,16.596 -2.82,23.962 3.403,23.962 3.403,20.035 -1.742,14.89
AGND on MidLayer2 "AGND_L03_P013" (solid, remove dead copper, pour order 13): 10.622,27.026 10.622,0.152 19.812,0.152 19.812,25.552 18.339,27.026
SW1 on MidLayer2 "SW1" (solid, remove dead copper, pour order 108): 3.53,22.682 3.53,22.689 3.803,22.962 8.31,22.962 8.59,22.682 8.59,21.789 9.326,21.053 9.326,16.916 8.564,16.154 1.944,16.154 1.503,16.596 1.503,17.958 3.535,19.99 3.535,22.682
SW1 on MidLayer2 "SW1_L03_P114" (solid, remove dead copper, pour order 114): 0.538,22.962 0.513,22.962 -0.327,22.121 -0.327,18.158 0.003,17.827 1.181,17.827 3.403,20.049 3.403,22.687 3.129,22.962
SW1 on MidLayer2 "SW1_L03_P112" (solid, remove dead copper, pour order 112): 0.538,22.962 0.513,22.962 -0.327,22.121 -0.327,18.158 0.003,17.827 1.181,17.827 3.403,20.049 3.403,22.687 3.129,22.962
AGND on MidLayer3 "AGND_L04_P059" (solid, remove dead copper, pour order 59): 10.761,26.982 18.359,27.03 19.812,25.577 19.812,0.152 10.761,0.152
PGND on MidLayer3 "NONET_L-01_P-001" (solid, pour order 128): -18.741,18.545 -10.904,18.545 -10.441,18.082 -10.441,11.748 -10.807,11.382 -14.787,11.382 -18.877,7.293 -18.877,0.152 -22.098,0.152 -22.098,0.153 -22.098,0.152 -22.606,0.152 -22.606,14.681
PGND on MidLayer3 "PGND_L04_P095" (solid, remove dead copper, pour order 95): 3.602,37.458 3.602,34.56 4.928,33.234 5.55,33.856 5.55,37.458
PGND on MidLayer3 "PGND_L04_P093" (solid, remove dead copper, pour order 93): 11.891,37.359 11.891,33.956 5.461,33.956 4.83,33.325 4.83,27.026 8.741,27.026 8.765,27.049 8.765,29.588 11.558,32.381 17.631,32.381 17.631,37.335 17.607,37.359
Vbulk+ on MidLayer3 "VBULK+_L04_P075" (solid, remove dead copper, pour order 75): -0.941,7.924 -0.941,5.673 -0.657,5.39 -0.637,5.41 0.83,5.41 0.83,0.152 7.818,0.152 7.818,5.385 9.41,5.385 9.41,7.924
SW1 on MidLayer3 "SW1" (solid, remove dead copper, pour order 110): 3.53,22.682 3.53,22.689 3.803,22.962 8.31,22.962 8.59,22.682 8.59,21.789 9.326,21.053 9.326,16.916 8.564,16.154 1.944,16.154 1.503,16.596 1.503,17.958 3.535,19.99 3.535,22.682
SW1 on MidLayer3 "SW1_L04_P116" (solid, remove dead copper, pour order 116): 0.538,22.962 0.513,22.962 -0.327,22.121 -0.327,18.158 0.003,17.827 1.181,17.827 3.403,20.049 3.403,22.687 3.129,22.962
PGND on MidLayer3 "PGND_L04_P120" (solid, remove dead copper, pour order 120): 1.43,15.232 6.135,15.232 6.513,14.855 6.513,12.344 5.37,11.201 -1.241,11.208 -1.636,10.813 -1.636,0.152 -8.613,0.152 -8.613,30.475 -4.773,34.315 3.758,34.315 4.631,33.466 4.631,27.551 -0.613,22.307 -0.599,22.293 -0.599,17.261
PGND on Top Layer "PGND_L01_P056" (solid, remove dead copper, pour order 56): 10.169,32.742 10.295,37.359 14.169,37.359 14.169,31.386 9.764,26.982 4.805,26.982 4.805,33.466
AGND on Top Layer "NONET_L-01_P-001" (solid, pour order 130): 16.97,16.827 19.33,16.827 19.812,16.21 19.812,0.152 12.04,0.152 11.018,1.174 11.018,25.178 11.622,25.781 12.727,25.781 13.173,24.892 16.501,24.883 16.97,24.566
SW1 on Top Layer "SW1_L01_P082" (solid, remove dead copper, pour order 82): -0.235,22.555 -0.478,22.312 -0.478,18.567 -0.26,18.349 -0.224,18.349 0.244,18.349 1.884,19.99 1.884,20.648 2.014,20.777 2.671,20.777 3.398,21.503 3.398,22.312 3.154,22.555
Vbulk+ on Top Layer "VBULK+_L01_P072" (solid, remove dead copper, pour order 72): -2.749,9.691 -2.782,9.657 -2.782,7.514 -0.657,5.39 -0.637,5.41 0.83,5.41 0.83,0.152 7.818,0.152 7.818,5.385 9.41,5.385 9.41,9.645 9.365,9.691
PGND on Top Layer "PGND_L01_P070" (solid, remove dead copper, pour order 70): 6.729,33.728 6.764,33.693 6.764,32.632 8.815,32.632 8.815,33.891 6.895,33.891 6.764,33.891
PGND on Top Layer "PGND_L01_P053" (solid, remove dead copper, pour order 53): -2.308,29.593 -2.308,33.956 0.261,36.525 4.67,36.525 4.67,29.593
PGND on Top Layer "PGND_L01_P030" (solid, remove dead copper, pour order 30): -3.116,15.164 7.866,15.164 9.617,13.413 9.617,11.21 -2.782,11.21 -3.078,11.505
SW1 on Top Layer "SW1" (solid, remove dead copper, pour order 100): 1.452,17.903 0.436,16.887 0.436,16.485 0.639,16.281 2.376,16.281 2.757,15.9 4.983,15.9 5.186,16.104 5.186,16.485 4.729,16.942 2.399,16.942 1.935,17.406 1.935,17.663 1.695,17.903
SW1 on Top Layer "SW1" (solid, remove dead copper, pour order 102): 2.645,22.682 -0.549,22.682 -0.941,22.29 -0.941,21.406 -1.24,21.107 -3.272,21.107 -3.78,20.599 -3.78,19.964 -3.907,19.837 -4.542,19.837 -4.796,20.091 -4.796,21.119 -4.398,21.517 -3.668,21.517 -2.637,22.547 -2.637,23.52 -1.977,24.181 7.326,24.181 7.701,23.806 7.701,22.475 7.326,22.101 7.326,21.717 7.021,21.412 3.83,21.412 3.535,21.707 3.535,22.403 3.256,22.682
PGND on MidLayer4 "PGND_L05_P096" (solid, remove dead copper, pour order 96): 7.32,33.956 7.247,33.956 4.221,36.982 -8.733,36.982 -14.321,31.394 -14.321,11.866 -13.96,11.505 -11.006,11.505 -10.638,11.873 -10.638,32.142 -7.575,35.204 3.543,35.204 4.83,33.916 4.83,27.026 8.741,27.026 8.765,27.049 8.765,29.588 11.558,32.381 17.631,32.381 17.631,37.335 17.607,37.359 11.891,37.359 11.891,33.956
SW1 on MidLayer4 "SW1_L05_P078" (solid, remove dead copper, pour order 78): 0.538,22.962 0.513,22.962 -0.327,22.121 -0.327,18.158 0.003,17.827 1.181,17.827 3.403,20.049 3.403,22.687 3.129,22.962
Vbulk+ on MidLayer4 "VBULK+_L05_P076" (solid, remove dead copper, pour order 76): -0.885,8.153 -0.885,5.617 -0.657,5.39 -0.637,5.41 0.83,5.41 0.83,0.153 7.818,0.153 7.818,5.385 9.41,5.385 9.41,8.153
AGND on MidLayer4 "AGND_L05_P060" (solid, remove dead copper, pour order 60): 10.622,27.026 10.622,0.53 11,0.152 19.812,0.152 19.812,25.571 18.357,27.026
SW1 on MidLayer4 "SW1" (solid, remove dead copper, pour order 104): 3.53,22.682 3.53,22.689 3.803,22.962 8.31,22.962 8.59,22.682 8.59,21.789 9.326,21.053 9.326,16.916 8.564,16.154 1.944,16.154 1.503,16.596 1.503,17.958 3.535,19.99 3.535,22.682
PGND on MidLayer4 "PGND_L05_P118" (solid, remove dead copper, pour order 118): 1.43,15.232 6.135,15.232 6.513,14.855 6.513,12.344 5.37,11.201 -1.241,11.208 -1.648,10.801 -1.648,0.153 -8.613,0.153 -8.613,30.475 -4.773,34.315 3.758,34.315 4.631,33.466 4.631,27.551 -0.769,22.151 -0.769,17.431
PGND on MidLayer1 "NONET_L-01_P-001" (solid, pour order 126): -18.741,18.545 -10.904,18.545 -10.441,18.082 -10.441,11.748 -10.807,11.382 -14.787,11.382 -18.877,7.293 -18.877,0.152 -22.606,0.152 -22.606,14.681
PGND on MidLayer1 "PGND_L02_P091" (solid, remove dead copper, pour order 91): 3.513,37.359 3.513,35.729 4.816,35.729 4.83,35.743 4.83,27.026 8.741,27.026 8.741,30.693 8.79,30.693 14.54,36.443 14.54,37.359
Vbulk+ on MidLayer1 "VBULK+_L02_P073" (solid, remove dead copper, pour order 73): -0.941,8.153 -0.941,5.692 -0.639,5.39 -0.618,5.41 0.83,5.41 0.83,0.152 7.818,0.152 7.818,5.385 9.429,5.385 9.429,8.153
AGND on MidLayer1 "AGND_L02_P058" (solid, remove dead copper, pour order 58): 10.761,26.72 10.78,26.739 10.78,27.004 18.361,27.004 19.812,25.552 19.812,0.153 11.018,0.153 10.761,0.41
SW1 on MidLayer1 "SW1" (solid, remove dead copper, pour order 106): 3.53,22.682 3.53,22.689 3.803,22.962 8.31,22.962 8.59,22.682 8.59,21.789 9.326,21.053 9.326,16.916 8.564,16.154 1.944,16.154 1.503,16.596 1.503,17.958 3.535,19.99 3.535,22.682
PGND on MidLayer1 "PGND_L02_P080" (solid, remove dead copper, pour order 80): 1.424,15.232 6.13,15.232 6.507,14.855 6.507,12.344 5.364,11.201 -1.247,11.208 -1.648,10.807 -1.648,0.152 -8.613,0.152 -8.613,30.481 -4.779,34.315 3.752,34.315 4.626,33.466 4.626,27.551 -0.619,22.307 -0.605,22.293 -0.605,17.261

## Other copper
Top Layer:
  region net SW1: -17.495,3.415 -10.41,3.415 -10.41,3.265 -10.41,0.109 -17.495,0.109
MidLayer3:
  region net SW1: -17.495,3.415 -10.41,3.415 -10.41,0.109 -17.495,0.109

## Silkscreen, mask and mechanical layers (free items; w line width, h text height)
Top Overlay:
  lines w0.254: -2.109,16.531 -0.147,16.522
  text "PMP41042 GaN DC" at -21.463,35.563 h1.85
  text "RevA" at -21.463,34.028 h1.85
Mechanical 1:
  lines w0.254: -23.084,0.09 20.32,0.155 20.32,4.312 20.253,37.458 -23.084,37.458 -23.084,12.979 -23.084,0.09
